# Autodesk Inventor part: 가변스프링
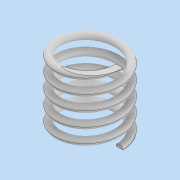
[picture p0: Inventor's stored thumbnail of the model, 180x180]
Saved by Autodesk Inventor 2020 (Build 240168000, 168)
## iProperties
Created: 2021-10
Part Number: 가변스프링
Material: 일반
Document SubType Name: Modeling
Designer: user
Density: 1 g/cm^3
Appearance: 기본값
Mass: 0.824199 g
Surface Area: 16.7339 cm^2
Volume: 0.824199 cm^3
Author: user
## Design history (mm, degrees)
sketch "스케치1"
  geometry: L1 (0, 0)-(8.5, 0); L2 (8.5, 0)-(8.5, 20.5); L3 (8.5, 20.5)-(0, 20.5); L4 (0, 20.5)-(0, 0); C1 r 1 at (8.5, 20.5)
  constraints: 8 end point, 2 parallel, 1 centre point, 1 coincident, 1 horizontal, 1 perpendicular
  dimensions: "d0" = 2 diameter of C1; "d1" = 17 diameter of L2 L4; "d2" = 20.5 distance between parallel lines of L1 L3 (derived)
feature "코일1" sketch "스케치1" pitch "d3" = 10; turns "d5" = 5; dims "d4" = 20.5 (= d2), "d6" = 0, angle "d7" = 90 deg, angle "d8" = 90 deg, "d9" = 0, "d10" = 0
sketch "스케치2"
  geometry: L1 (20.5, 11.854)-(0, 11.854); L2 (0, 11.854)-(0, -11.854); L3 (0, -11.854)-(20.5, -11.854); L4 (20.5, -11.854)-(20.5, 11.854); 2 further points
  constraints: 8 end point, 2 parallel, 1 coincident, 1 horizontal, 1 midpoint, 1 perpendicular
  dimensions: "d11" = 20.5 distance between parallel lines of L2 L4 (= d2)
extrude "돌출1" sketch "스케치2" stored distance "d12" = 32.5; taper "d13" = 0 deg
node "솔리드1"
